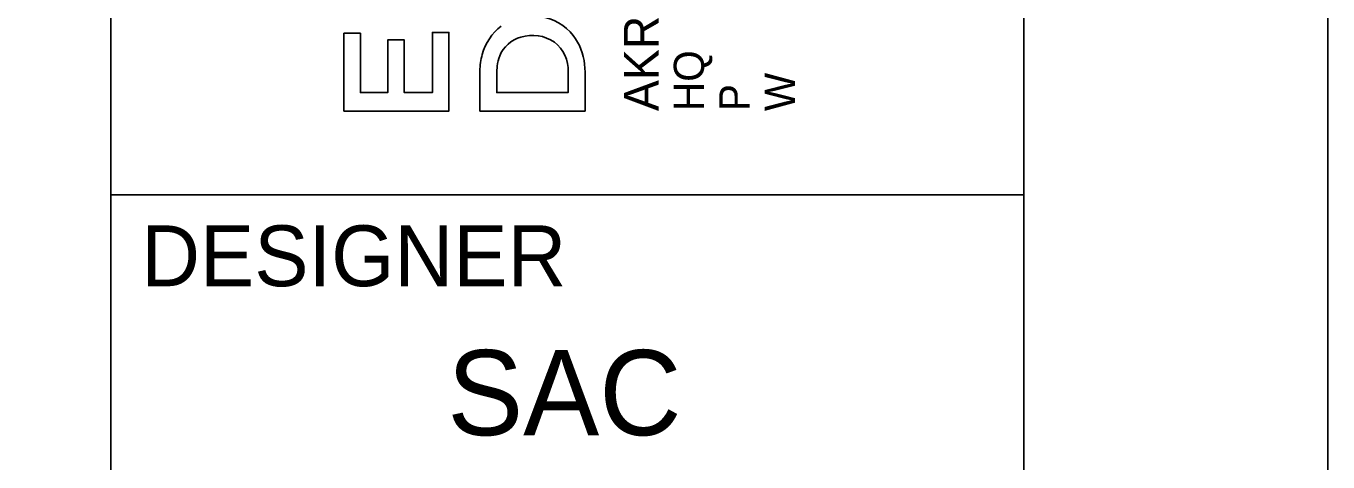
# Model space of a CAD drawing. Extents: x -0.2 to 34, y 0 to 22.
# Drawn here: x 31.861 to 34, y 2.061 to 2.778 of the extents above; entities that cross this region are included whole.
import ezdxf

# ---------------------------------------------------------------- set-up
doc = ezdxf.new("R2010")
doc.units = 0
for name, color, linetype in [('SH_Border', 7, 'Continuous'), ('SH_Cut_Line', 7, 'Continuous'), ('SH_Named_Boundary', 7, 'Continuous')]:
    doc.layers.add(name, color=color, linetype=linetype)

msp = doc.modelspace()

# ---------------------------------------------------------------- linework, layer by layer
at = {"layer": 'SH_Border'}
for p, q in [((32.383, 2.6379), (32.383, 2.766)), ((32.383, 2.766), (32.4101, 2.766)), ((32.4101, 2.766), (32.4101, 2.6683)), ((32.5286, 2.6683), (32.5286, 2.7672)), ((32.5286, 2.7672), (32.5557, 2.7672)), ((32.5557, 2.7672), (32.5557, 2.6379)), ((32.455, 2.6683), (32.455, 2.7549)), ((32.455, 2.7549), (32.4822, 2.7549)), ((32.4822, 2.7549), (32.4822, 2.6683)), ((32.6064, 2.638), (32.6064, 2.704)), ((32.6347, 2.7118), (32.6341, 2.7023)), ((32.6341, 2.7023), (32.6341, 2.6684)), ((32.7515, 2.6683), (32.7515, 2.7024)), ((32.7785, 2.715), (32.7792, 2.7021)), ((32.7792, 2.7021), (32.7792, 2.638)), ((32.4101, 2.6683), (32.455, 2.6683)), ((32.4822, 2.6683), (32.5286, 2.6683)), ((32.6341, 2.6684), (32.7515, 2.6683)), ((32.5557, 2.6379), (32.383, 2.6379)), ((32.7792, 2.638), (32.6064, 2.638))]:
    msp.add_line(p, q, dxfattribs=at)
msp.add_lwpolyline([(32.383, 2.6379), (32.383, 2.766), (32.4101, 2.766), (32.4101, 2.6683), (32.455, 2.6683), (32.455, 2.7549), (32.4822, 2.7549), (32.4822, 2.6683), (32.5286, 2.6683), (32.5286, 2.7672), (32.5557, 2.7672), (32.5557, 2.6379)], close=True, dxfattribs=at)
for points in [[(32.7785, 2.715), (32.7792, 2.7021), (32.7792, 2.638), (32.6064, 2.638)], [(32.6064, 2.638), (32.6064, 2.704)], [(32.6347, 2.7118), (32.6341, 2.7023), (32.6341, 2.6684), (32.7515, 2.6683), (32.7515, 2.7024)]]:
    msp.add_lwpolyline(points, dxfattribs=at)
for centre, radius, start, end in [((32.6946, 2.7113), 0.0827, 37.8521, 82.402), ((32.6946, 2.7113), 0.0827, 37.8521, 82.402), ((32.6939, 2.7089), 0.0865, 127.2362, 165.148), ((32.6939, 2.7089), 0.0865, 127.2362, 165.148), ((32.6928, 2.6986), 0.0639, 55.6727, 107.2093), ((32.6928, 2.6986), 0.0639, 55.6727, 107.2093), ((32.6859, 2.7057), 0.0931, 5.7333, 37.304), ((32.6859, 2.7057), 0.0931, 5.7333, 37.304), ((32.6889, 2.7078), 0.054, 106.1881, 157.3861), ((32.6889, 2.7078), 0.054, 106.1881, 157.3861), ((32.6929, 2.705), 0.0587, 357.4662, 52.2665), ((32.6929, 2.705), 0.0587, 357.4662, 52.2665), ((32.7143, 2.7028), 0.1078, 164.7861, 179.3704), ((32.7143, 2.7028), 0.1078, 164.7861, 179.3704), ((32.6983, 2.7039), 0.0641, 157.3571, 172.9275), ((32.6983, 2.7039), 0.0641, 157.3571, 172.9275)]:
    msp.add_arc(centre, radius, start, end, dxfattribs=at)
at = {"layer": 'SH_Cut_Line'}
for p, q in [((32, 0.5), (32, 21.5)), ((32, 2.5), (33.5, 2.5))]:
    msp.add_line(p, q, dxfattribs=at)
msp.add_lwpolyline([(1.5, 21.5), (33.5, 21.5), (33.5, 0.5), (1.5, 0.5)], close=True, dxfattribs=at)
at = {"layer": 'SH_Named_Boundary'}
msp.add_lwpolyline([(0, 0), (34, 0), (34, 22), (0, 22)], close=True, dxfattribs=at)

# ---------------------------------------------------------------- texts
at = {"layer": 'SH_Border'}
for s, height, p in [('AKRON / CLEVELAND / COLUMBUS', 0.056969, (32.9001, 2.638)), ('HQ ', 0.04985, (32.9749, 2.638)), ('W', 0.0498, (33.1244, 2.638)), ('P', 0.0498, (33.0497, 2.638))]:
    msp.add_text(s, height=height, rotation=90, dxfattribs=at).set_placement(p)
for s, height, p in [('DESIGNER', 0.1, (32.05, 2.35)), ('SAC', 0.14, (32.5528, 2.105))]:
    msp.add_text(s, height=height, dxfattribs=at).set_placement(p)

doc.saveas('drawing.dxf')
